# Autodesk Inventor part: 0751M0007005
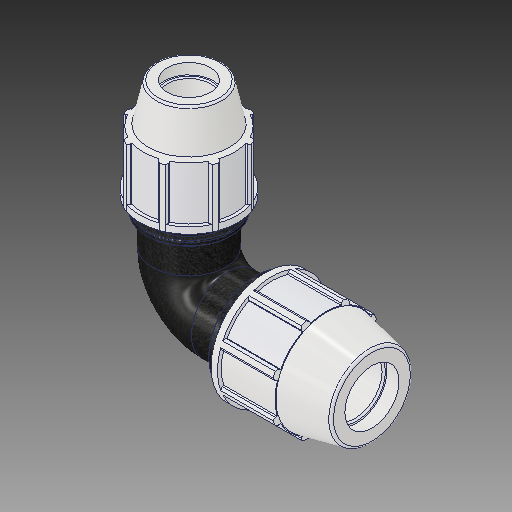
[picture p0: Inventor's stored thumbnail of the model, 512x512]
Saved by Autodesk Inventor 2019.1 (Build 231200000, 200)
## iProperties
Created: 2017-02
Part Number: 0751M0007005
Material: PVC-Piping
Description: PLASSON REDUCING ELBOW 3/4'' - 1/2''
Document SubType Name: Modeling
Designer: KIM
Mass: 92.6774 g
Surface Area: 199.44 cm^2
Volume: 66.1981 cm^3
Density: 1.4 g/cm^3
Appearance: PTFE
Author: KIM
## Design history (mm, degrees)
derived "0751M0.ipt"
feature "Solid1::0751M0.ipt"
tag "TaggingFeature1"
body "Solid1"
other parameters: "d_" = 26.6, "E_" = 53.848, "A_" = 89.916, "l_" = 57.912, "E_1" = 48.006, "l_1" = 56.896, "A_1" = 74.93, "d_1" = 21.2, "d2" = 26.6, "d4" = 7.493, "d5" = 22.479, "d7" = 53.848, "d9" = 12.84514, "d11" = 2.9972, "d13" = 120 deg, "d14" = 39.9, "d15" = 12 deg, "d16" = 46.84776, "d18" = 1.33, "d19" = 35 deg, "d20" = 17.5 deg, "d21" = 50.07864, "d23" = 0, "d25" = 360 deg, "d27" = 1.07696, "d33" = 0.532, "d42" = 29.67228, "d43" = 1.61544, "d46" = 0.798, "d51" = 89.916, "d63" = 57.912, "d67" = 40.386, "d76" = 21.2, "d77" = 48.006, "d78" = 12 deg, "d79" = 89.916, "d80" = 120 deg, "d81" = 31.8, "d82" = 6.24417, "d84" = 56.896, "d85" = 36.0045, "d86" = 41.76522, "d87" = 2.49767, "d88" = 0.49953, "d89" = 18.7325, "d90" = 29.972, "d92" = 19.2024, "d93" = 0, "d94" = 0, "d95" = 2.6924, "d96" = 0.59944, "d97" = 2.6924, "d98" = 44.64558, "d99" = 35 deg, "d100" = 17.5 deg, "d102" = 0, "d103" = 0.96012, "d107" = 360 deg, "d109" = 0.636, "d112" = 1.06, "d113" = 3.2004, "d114" = 0, "d115" = 3.2004, "d116" = 0
